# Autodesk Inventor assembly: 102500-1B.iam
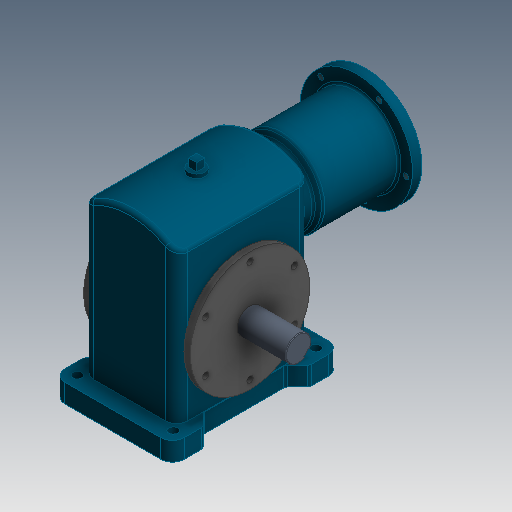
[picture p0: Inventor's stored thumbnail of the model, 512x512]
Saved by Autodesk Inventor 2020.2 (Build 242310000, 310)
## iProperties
Created: 2000-10
Part Number: 102500-1B.iam
Document SubType Name: Assembly
Designer: wymerj
Mass: 19938 g
Surface Area: 7536.59 cm^2
Volume: 3591.38 cm^3
Density: 5.55163 g/cm^3
Control State: 0
Master: False
Checked Out: False
Shininess: 0.0
Length Units: 11269
Angle Units: 11279
Time Units: 11290
Mass Units: 11283
Length Display Precision: 3
Angle Display Precision: 2
Compacted: True
Dimensions: 291,8x377x254 mm
Mass: 19,938 kg
DocNumber: 102500-1B.iam
Folder: 01 - Themengebiete\Simplification\01 - Packaging machine\
VDS_Category: 3D Komponenten
VDS_NumSchm: Kein
Density: 0.0
Volumn: 0.0
Area: 0.0
PropertySet Name: Model Information
Author: wymerj
Revision Number: -
Title: 102500-1A
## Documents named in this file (10)
- D:\07 - DEMODATEN\OTX 2019 - Dataset - UPDATE - Dez2019\Designs\07-Packing machine\102500-1B.iam
- D:\07 - DEMODATEN\OTX 2019 - Dataset - UPDATE - Dez2019\Designs\07-Packing machine\Parts\ADSK-011841.ipt
- D:\07 - DEMODATEN\OTX 2019 - Dataset - UPDATE - Dez2019\Designs\07-Packing machine\Parts\ADSK-011827.ipt
- D:\07 - DEMODATEN\OTX 2019 - Dataset - UPDATE - Dez2019\Designs\07-Packing machine\Parts\ADSK-011237.ipt
- D:\07 - DEMODATEN\OTX 2019 - Dataset - UPDATE - Dez2019\Designs\07-Packing machine\Parts\ADSK-011238.ipt
- D:\07 - DEMODATEN\OTX 2019 - Dataset - UPDATE - Dez2019\Designs\07-Packing machine\Parts\ADSK-011241.ipt
- D:\07 - DEMODATEN\OTX 2019 - Dataset - UPDATE - Dez2019\Designs\07-Packing machine\Parts\ADSK-011710.ipt
- D:\07 - DEMODATEN\OTX 2019 - Dataset - UPDATE - Dez2019\Designs\07-Packing machine\Parts\ADSK-011240.ipt
- D:\07 - DEMODATEN\OTX 2019 - Dataset - UPDATE - Dez2019\Designs\07-Packing machine\Parts\ADSK-011242.ipt
- D:\07 - DEMODATEN\OTX 2019 - Dataset - UPDATE - Dez2019\Designs\07-Packing machine\Parts\ADSK-011243.ipt
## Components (10 placed, 9 different names)
1. ADSK-011827:1 — Flush:7, Flush:1, Mate:1, Mate:2, Mate:5, Angle:1, Mate:6, Fluchtend:3, Insert:1, Angle:2
2. ADSK-011841:1 — Flush:7, Flush:1, Mate:1, Mate:3, Mate:4, Flush:9, Passend:14
3. ADSK-011841:2 — Mate:2, Mate:3, Mate:4, Mate:8
4. ADSK-011237:1 — Mate:5, Angle:1, Mate:6, Rotation:1, Mate:9, Mate:10, Mate:13
5. ADSK-011238:1 — Flush:2, Rotation:1, Rotation:2, Insert:1
6. ADSK-011240:2 — Flush:2, Rotation:2, Mate:8, Passend:15
7. ADSK-011241:1 — Fluchtend:3, Passend:12, Passend:15, Passend:14
8. ADSK-011242:1 — Flush:8, Mate:9, Mate:10, Flush:4, Mate:11, Mate:13, Flush:6
9. ADSK-011243:1 — Flush:8, Flush:4, Mate:11, Flush:6, Angle:2
10. ADSK-011710:1 — Flush:9, Passend:12
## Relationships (27: Mate 14, Flush 8, Angle 2, RelateRotation 2, Insert 1)
- Flush:7: ADSK-011827:1 ↔ ADSK-011841:1
- Flush:1: ADSK-011827:1 ↔ ADSK-011841:1
- Mate:1: ADSK-011827:1 ↔ ADSK-011841:1
- Mate:2: ADSK-011827:1 ↔ ADSK-011841:2
- Mate:3: ADSK-011841:1 ↔ ADSK-011841:2
- Mate:4: ADSK-011841:1 ↔ ADSK-011841:2
- Mate:5: ADSK-011827:1 ↔ ADSK-011237:1
- Angle:1: ADSK-011827:1 ↔ ADSK-011237:1
- Mate:6: ADSK-011827:1 ↔ ADSK-011237:1
- Flush:2: ADSK-011238:1 ↔ ADSK-011240:2
- Rotation:1 [RelateRotation]: ADSK-011237:1 ↔ ADSK-011238:1
- Rotation:2 [RelateRotation]: ADSK-011238:1 ↔ ADSK-011240:2
- Fluchtend:3 [Flush]: ADSK-011827:1 ↔ ADSK-011241:1
- Mate:8: ADSK-011841:2 ↔ ADSK-011240:2
- Flush:8: ADSK-011242:1 ↔ ADSK-011243:1
- Mate:9: ADSK-011237:1 ↔ ADSK-011242:1
- Mate:10: ADSK-011237:1 ↔ ADSK-011242:1
- Flush:4: ADSK-011242:1 ↔ ADSK-011243:1
- Mate:11: ADSK-011242:1 ↔ ADSK-011243:1
- Flush:9: ADSK-011841:1 ↔ ADSK-011710:1
- Passend:12 [Mate]: ADSK-011241:1 ↔ ADSK-011710:1
- Passend:15 [Mate]: ADSK-011240:2 ↔ ADSK-011241:1
- Insert:1: ADSK-011827:1 ↔ ADSK-011238:1
- Mate:13: ADSK-011237:1 ↔ ADSK-011242:1
- Flush:6: ADSK-011242:1 ↔ ADSK-011243:1
- Angle:2: ADSK-011827:1 ↔ ADSK-011243:1
- Passend:14 [Mate]: ADSK-011841:1 ↔ ADSK-011241:1
